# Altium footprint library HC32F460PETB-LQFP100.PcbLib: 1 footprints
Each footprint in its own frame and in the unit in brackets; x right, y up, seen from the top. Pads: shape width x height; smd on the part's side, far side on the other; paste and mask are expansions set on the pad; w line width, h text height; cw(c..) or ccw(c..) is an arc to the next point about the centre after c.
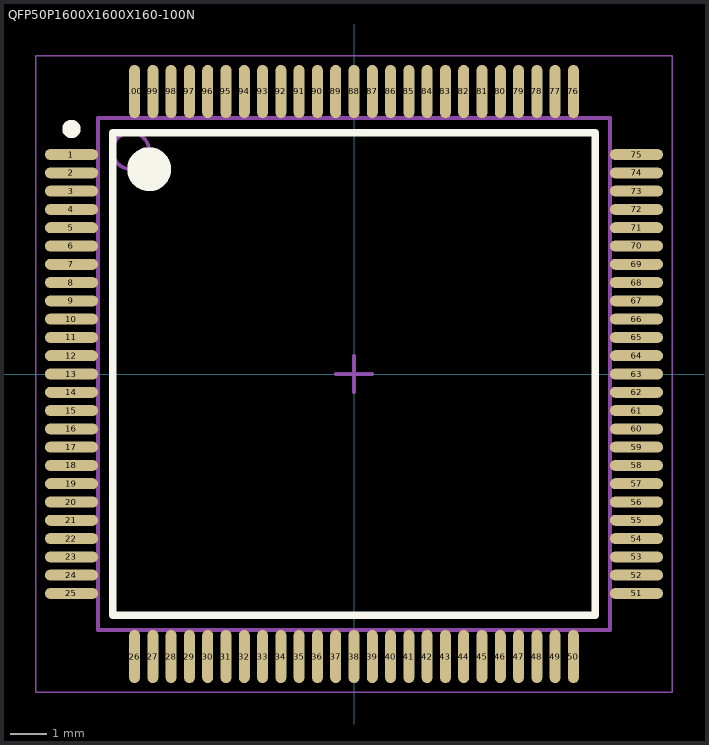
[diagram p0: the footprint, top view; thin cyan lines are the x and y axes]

## QFP50P1600X1600X160-100N [mm] "TSQFP, 100-Leads, Body 14.00x14.00mm, Pitch 0.50mm, IPC Medium Density,ZLGLIB"
height 1.6
pads (100):
  oval 1.45x0.3 smd mask+0.051: 1(-7.725,6) 2(-7.725,5.5) 3(-7.725,5) 4(-7.725,4.5) 5(-7.725,4) 6(-7.725,3.5) 7(-7.725,3) 8(-7.725,2.5) 9(-7.725,2) 10(-7.725,1.5) 11(-7.725,1) 12(-7.725,0.5) 13(-7.725,0) 14(-7.725,-0.5) 15(-7.725,-1) 16(-7.725,-1.5) 17(-7.725,-2) 18(-7.725,-2.5) 19(-7.725,-3) 20(-7.725,-3.5) 21(-7.725,-4) 22(-7.725,-4.5) 23(-7.725,-5) 24(-7.725,-5.5) 25(-7.725,-6) 51(7.725,-6) 52(7.725,-5.5) 53(7.725,-5) 54(7.725,-4.5) 55(7.725,-4) 56(7.725,-3.5) 57(7.725,-3) 58(7.725,-2.5) 59(7.725,-2) 60(7.725,-1.5) 61(7.725,-1) 62(7.725,-0.5) 63(7.725,0) 64(7.725,0.5) 65(7.725,1) 66(7.725,1.5) 67(7.725,2) 68(7.725,2.5) 69(7.725,3) 70(7.725,3.5) 71(7.725,4) 72(7.725,4.5) 73(7.725,5) 74(7.725,5.5) 75(7.725,6)
  oval 0.3x1.45 smd mask+0.051: 26(-6,-7.725) 27(-5.5,-7.725) 28(-5,-7.725) 29(-4.5,-7.725) 30(-4,-7.725) 31(-3.5,-7.725) 32(-3,-7.725) 33(-2.5,-7.725) 34(-2,-7.725) 35(-1.5,-7.725) 36(-1,-7.725) 37(-0.5,-7.725) 38(0,-7.725) 39(0.5,-7.725) 40(1,-7.725) 41(1.5,-7.725) 42(2,-7.725) 43(2.5,-7.725) 44(3,-7.725) 45(3.5,-7.725) 46(4,-7.725) 47(4.5,-7.725) 48(5,-7.725) 49(5.5,-7.725) 50(6,-7.725) 76(6,7.725) 77(5.5,7.725) 78(5,7.725) 79(4.5,7.725) 80(4,7.725) 81(3.5,7.725) 82(3,7.725) 83(2.5,7.725) 84(2,7.725) 85(1.5,7.725) 86(1,7.725) 87(0.5,7.725) 88(0,7.725) 89(-0.5,7.725) 90(-1,7.725) 91(-1.5,7.725) 92(-2,7.725) 93(-2.5,7.725) 94(-3,7.725) 95(-3.5,7.725) 96(-4,7.725) 97(-4.5,7.725) 98(-5,7.725) 99(-5.5,7.725) 100(-6,7.725)
Top Overlay:
  circle w0.25: c-7.725,6.7 r0.125
  circle w0.6: c-5.6,5.6 r0.3
  lines w0.2: -6.6,-6.6 -6.6,6.6 6.6,6.6 6.6,-6.6 -6.6,-6.6
Mechanical 13:
  circle w0.1: c-6.1,6.1 r0.5
  lines w0.1: -7,-7 -7,7 7,7 7,-7 -7,-7
Mechanical 15:
  lines w0.05: -8.7,-8.7 -8.7,8.7 8.7,8.7 8.7,-8.7 -8.7,-8.7
  lines w0.1: -0.5,0 0.5,0 ; 0,-0.5 0,0.5
3D body: height 1.6, standoff 0, extent -8,-8 8,8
